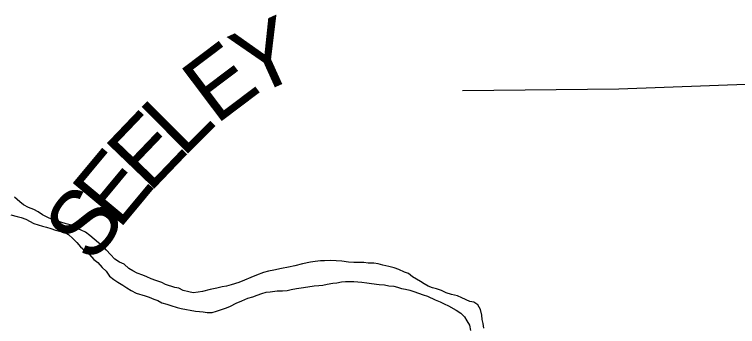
# Model space of a CAD drawing. Extents: x -59 to 82, y -3 to 49.
# Drawn here: x -49.598 to -48.973, y 45.667 to 45.937 of the extents above; entities that cross this region are included whole.
import ezdxf

# ---------------------------------------------------------------- set-up
doc = ezdxf.new("R2010")
doc.units = 0
for name, color, linetype in [('GM_X_Minor_River', 7, 'Continuous'), ('GM_X_Township_Road', 7, 'Continuous'), ('GM_X_Township_Road_Text', 7, 'Continuous')]:
    doc.layers.add(name, color=color, linetype=linetype)

msp = doc.modelspace()

# ---------------------------------------------------------------- linework, layer by layer
at = {"layer": 'GM_X_Minor_River'}
for p, q in [((-49.59374, 45.77475), (-49.59829, 45.77854)), ((-49.59033, 45.77211), (-49.59374, 45.77475)), ((-49.58616, 45.76984), (-49.59033, 45.77211)), ((-49.58161, 45.76795), (-49.58616, 45.76984)), ((-49.57782, 45.76606), (-49.58161, 45.76795)), ((-49.60129, 45.76337), (-49.59598, 45.76186)), ((-49.59598, 45.76186), (-49.59257, 45.76111)), ((-49.59257, 45.76111), (-49.58841, 45.7596)), ((-49.57403, 45.76341), (-49.57782, 45.76606)), ((-49.56834, 45.76039), (-49.57403, 45.76341)), ((-49.56304, 45.75888), (-49.56834, 45.76039)), ((-49.58841, 45.7596), (-49.58158, 45.75582)), ((-49.58158, 45.75582), (-49.57401, 45.75356)), ((-49.55811, 45.75699), (-49.56304, 45.75888)), ((-49.55357, 45.75548), (-49.55811, 45.75699)), ((-49.55016, 45.75473), (-49.55357, 45.75548)), ((-49.54523, 45.75208), (-49.55016, 45.75473)), ((-49.57401, 45.75356), (-49.5706, 45.7528)), ((-49.5706, 45.7528), (-49.56681, 45.75167)), ((-49.56681, 45.75167), (-49.56264, 45.75016)), ((-49.56264, 45.75016), (-49.55924, 45.74941)), ((-49.55924, 45.74941), (-49.55583, 45.74903)), ((-49.55583, 45.74903), (-49.55166, 45.74639)), ((-49.54069, 45.75019), (-49.54523, 45.75208)), ((-49.5369, 45.7483), (-49.54069, 45.75019)), ((-49.53311, 45.74566), (-49.5369, 45.7483)), ((-49.55166, 45.74639), (-49.54786, 45.74298)), ((-49.54786, 45.74298), (-49.54445, 45.73957)), ((-49.52931, 45.74225), (-49.53311, 45.74566)), ((-49.52552, 45.73922), (-49.52931, 45.74225)), ((-49.54445, 45.73957), (-49.54104, 45.73579)), ((-49.54104, 45.73579), (-49.53345, 45.72898)), ((-49.52173, 45.73657), (-49.52552, 45.73922)), ((-49.51869, 45.73279), (-49.52173, 45.73657)), ((-49.53345, 45.72898), (-49.52965, 45.72481)), ((-49.51528, 45.729), (-49.51869, 45.73279)), ((-49.51148, 45.72522), (-49.51528, 45.729)), ((-49.52965, 45.72481), (-49.52624, 45.72216)), ((-49.50731, 45.72257), (-49.51148, 45.72522)), ((-49.3381, 45.72321), (-49.34226, 45.72244)), ((-49.33355, 45.72359), (-49.3381, 45.72321)), ((-49.33015, 45.7236), (-49.33355, 45.72359)), ((-49.32522, 45.72399), (-49.33015, 45.7236)), ((-49.31992, 45.72361), (-49.32522, 45.72399)), ((-49.315, 45.72324), (-49.31992, 45.72361)), ((-49.30932, 45.72249), (-49.315, 45.72324)), ((-49.52624, 45.72216), (-49.52245, 45.718)), ((-49.52245, 45.718), (-49.51903, 45.71459)), ((-49.50352, 45.72068), (-49.50731, 45.72257)), ((-49.49935, 45.7169), (-49.50352, 45.72068)), ((-49.49594, 45.71501), (-49.49935, 45.7169)), ((-49.36723, 45.7171), (-49.37404, 45.71557)), ((-49.36118, 45.71824), (-49.36723, 45.7171)), ((-49.35588, 45.71939), (-49.36118, 45.71824)), ((-49.34907, 45.72092), (-49.35588, 45.71939)), ((-49.34226, 45.72244), (-49.34907, 45.72092)), ((-49.30478, 45.72212), (-49.30932, 45.72249)), ((-49.29607, 45.72214), (-49.30478, 45.72212)), ((-49.29228, 45.72176), (-49.29607, 45.72214)), ((-49.28736, 45.72177), (-49.29228, 45.72176)), ((-49.28358, 45.72102), (-49.28736, 45.72177)), ((-49.27979, 45.71989), (-49.28358, 45.72102)), ((-49.27448, 45.71876), (-49.27979, 45.71989)), ((-49.26994, 45.71763), (-49.27448, 45.71876)), ((-49.26577, 45.71612), (-49.26994, 45.71763)), ((-49.51903, 45.71459), (-49.516, 45.71043)), ((-49.516, 45.71043), (-49.5122, 45.7074)), ((-49.49215, 45.71312), (-49.49594, 45.71501)), ((-49.48723, 45.71123), (-49.49215, 45.71312)), ((-49.48382, 45.70972), (-49.48723, 45.71123)), ((-49.3888, 45.71138), (-49.39372, 45.7091)), ((-49.38275, 45.71366), (-49.3888, 45.71138)), ((-49.37858, 45.71481), (-49.38275, 45.71366)), ((-49.37404, 45.71557), (-49.37858, 45.71481)), ((-49.26085, 45.71385), (-49.26577, 45.71612)), ((-49.25744, 45.71272), (-49.26085, 45.71385)), ((-49.25402, 45.70969), (-49.25744, 45.71272)), ((-49.5122, 45.7074), (-49.50879, 45.70513)), ((-49.50879, 45.70513), (-49.50462, 45.70248)), ((-49.48003, 45.70821), (-49.48382, 45.70972)), ((-49.47586, 45.7067), (-49.48003, 45.70821)), ((-49.47093, 45.70481), (-49.47586, 45.7067)), ((-49.46752, 45.7033), (-49.47093, 45.70481)), ((-49.40431, 45.70491), (-49.41074, 45.703)), ((-49.39939, 45.70681), (-49.40431, 45.70491)), ((-49.39372, 45.7091), (-49.39939, 45.70681)), ((-49.32783, 45.70351), (-49.32291, 45.70428)), ((-49.32291, 45.70428), (-49.31951, 45.70466)), ((-49.31951, 45.70466), (-49.31534, 45.70542)), ((-49.31534, 45.70542), (-49.31194, 45.70581)), ((-49.31194, 45.70581), (-49.30815, 45.70581)), ((-49.30815, 45.70581), (-49.30474, 45.70582)), ((-49.30474, 45.70582), (-49.29793, 45.70507)), ((-49.29793, 45.70507), (-49.29338, 45.7047)), ((-49.29338, 45.7047), (-49.2896, 45.70395)), ((-49.2896, 45.70395), (-49.28278, 45.7032)), ((-49.2472, 45.70591), (-49.25402, 45.70969)), ((-49.24379, 45.70364), (-49.2472, 45.70591)), ((-49.50462, 45.70248), (-49.50121, 45.70021)), ((-49.50121, 45.70021), (-49.49742, 45.69794)), ((-49.49742, 45.69794), (-49.49287, 45.69568)), ((-49.45957, 45.70066), (-49.46752, 45.7033)), ((-49.45616, 45.6999), (-49.45957, 45.70066)), ((-49.45237, 45.69801), (-49.45616, 45.6999)), ((-49.44744, 45.69688), (-49.45237, 45.69801)), ((-49.4289, 45.69881), (-49.43571, 45.69728)), ((-49.42322, 45.69995), (-49.4289, 45.69881)), ((-49.41868, 45.7011), (-49.42322, 45.69995)), ((-49.4149, 45.70186), (-49.41868, 45.7011)), ((-49.41074, 45.703), (-49.4149, 45.70186)), ((-49.37703, 45.69699), (-49.37097, 45.69776)), ((-49.37097, 45.69776), (-49.36643, 45.69777)), ((-49.36643, 45.69777), (-49.36227, 45.69815)), ((-49.36227, 45.69815), (-49.35886, 45.69891)), ((-49.35886, 45.69891), (-49.35432, 45.69968)), ((-49.35432, 45.69968), (-49.35016, 45.70044)), ((-49.35016, 45.70044), (-49.34448, 45.70121)), ((-49.34448, 45.70121), (-49.33918, 45.70198)), ((-49.33918, 45.70198), (-49.33502, 45.70236)), ((-49.33502, 45.70236), (-49.33161, 45.70275)), ((-49.33161, 45.70275), (-49.32783, 45.70351)), ((-49.28278, 45.7032), (-49.27824, 45.70283)), ((-49.27824, 45.70283), (-49.27445, 45.70208)), ((-49.27445, 45.70208), (-49.27029, 45.7017)), ((-49.27029, 45.7017), (-49.26688, 45.70095)), ((-49.26688, 45.70095), (-49.26347, 45.69982)), ((-49.26347, 45.69982), (-49.26006, 45.69907)), ((-49.26006, 45.69907), (-49.25627, 45.69831)), ((-49.25627, 45.69831), (-49.25286, 45.69718)), ((-49.24038, 45.70175), (-49.24379, 45.70364)), ((-49.23659, 45.70024), (-49.24038, 45.70175)), ((-49.23318, 45.69949), (-49.23659, 45.70024)), ((-49.22901, 45.69798), (-49.23318, 45.69949)), ((-49.22484, 45.69609), (-49.22901, 45.69798)), ((-49.49287, 45.69568), (-49.4853, 45.69341)), ((-49.4853, 45.69341), (-49.48189, 45.69228)), ((-49.48189, 45.69228), (-49.47772, 45.69039)), ((-49.44366, 45.69613), (-49.44744, 45.69688)), ((-49.43949, 45.69652), (-49.44366, 45.69613)), ((-49.43571, 45.69728), (-49.43949, 45.69652)), ((-49.39633, 45.69127), (-49.39216, 45.69242)), ((-49.39216, 45.69242), (-49.38838, 45.69394)), ((-49.38838, 45.69394), (-49.38422, 45.69546)), ((-49.38422, 45.69546), (-49.38044, 45.69661)), ((-49.38044, 45.69661), (-49.37703, 45.69699)), ((-49.25286, 45.69718), (-49.24869, 45.69567)), ((-49.24869, 45.69567), (-49.2449, 45.69416)), ((-49.2449, 45.69416), (-49.24112, 45.69303)), ((-49.24112, 45.69303), (-49.23429, 45.69001)), ((-49.2203, 45.69458), (-49.22484, 45.69609)), ((-49.215, 45.69345), (-49.2203, 45.69458)), ((-49.21121, 45.69156), (-49.215, 45.69345)), ((-49.20439, 45.68854), (-49.21121, 45.69156)), ((-49.47772, 45.69039), (-49.47431, 45.68926)), ((-49.47431, 45.68926), (-49.4709, 45.68737)), ((-49.4709, 45.68737), (-49.46635, 45.68624)), ((-49.46635, 45.68624), (-49.46294, 45.68511)), ((-49.41145, 45.68443), (-49.40654, 45.68709)), ((-49.40654, 45.68709), (-49.40162, 45.68899)), ((-49.40162, 45.68899), (-49.39633, 45.69127)), ((-49.23429, 45.69001), (-49.23013, 45.68812)), ((-49.23013, 45.68812), (-49.22672, 45.68661)), ((-49.22672, 45.68661), (-49.22293, 45.68472)), ((-49.20098, 45.68779), (-49.20439, 45.68854)), ((-49.19757, 45.68552), (-49.20098, 45.68779)), ((-49.19529, 45.68173), (-49.19757, 45.68552)), ((-49.46294, 45.68511), (-49.45764, 45.68322)), ((-49.45764, 45.68322), (-49.45423, 45.68247)), ((-49.45423, 45.68247), (-49.44173, 45.68021)), ((-49.44173, 45.68021), (-49.43832, 45.67984)), ((-49.43832, 45.67984), (-49.43492, 45.67946)), ((-49.43492, 45.67946), (-49.43151, 45.67909)), ((-49.43151, 45.67909), (-49.42734, 45.6791)), ((-49.42734, 45.6791), (-49.42356, 45.68024)), ((-49.42356, 45.68024), (-49.41826, 45.68176)), ((-49.41826, 45.68176), (-49.41486, 45.68291)), ((-49.41486, 45.68291), (-49.41145, 45.68443)), ((-49.22293, 45.68472), (-49.21611, 45.68094)), ((-49.21611, 45.68094), (-49.21232, 45.67829)), ((-49.19414, 45.67681), (-49.19529, 45.68173)), ((-49.21232, 45.67829), (-49.2089, 45.67527)), ((-49.2089, 45.67527), (-49.207, 45.67186)), ((-49.19375, 45.67302), (-49.19414, 45.67681)), ((-49.19299, 45.6696), (-49.19375, 45.67302)), ((-49.207, 45.67186), (-49.20472, 45.66807)), ((-49.20472, 45.66807), (-49.20395, 45.66352)), ((-49.19222, 45.66544), (-49.19299, 45.6696))]:
    msp.add_line(p, q, dxfattribs=at)
at = {"layer": 'GM_X_Township_Road'}
for p, q in [((-49.07564, 45.87216), (-48.86943, 45.87988)), ((-49.21077, 45.8707), (-49.07564, 45.87216))]:
    msp.add_line(p, q, dxfattribs=at)

# ---------------------------------------------------------------- texts
at = {"layer": 'GM_X_Township_Road_Text'}
for s, rotation, p in [('Y', 24.31793, (-49.39292, 45.86457)), ('E', 37.01046, (-49.424, 45.84068)), ('L', 44.98484, (-49.45249, 45.81201)), ('E', 46.22441, (-49.48166, 45.78155)), ('E', 50.21967, (-49.50816, 45.74967)), ('S', 52.62927, (-49.53103, 45.7197))]:
    msp.add_text(s, height=0.05682, rotation=rotation, dxfattribs=at).set_placement(p)

doc.saveas('drawing.dxf')
